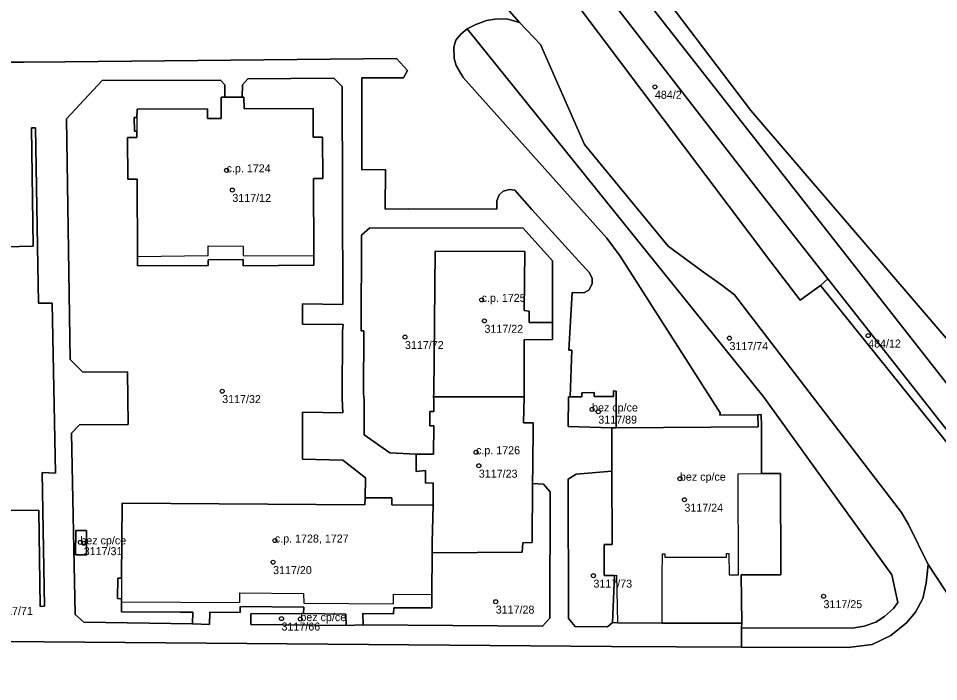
# Model space of a CAD drawing. Extents: x -878211 to -870363, y -1058464 to -1052522.
# Drawn here: x -874067.3 to -873952.4, y -1056770.5 to -1056687.6 of the extents above; entities that cross this region are included whole.
import ezdxf

# ---------------------------------------------------------------- set-up
doc = ezdxf.new("R2010")
doc.units = 0
for name, color, linetype in [('Vrstva 50', 7, 'Continuous'), ('Vrstva 51', 7, 'Continuous'), ('Vrstva 52', 7, 'Continuous')]:
    doc.layers.add(name, color=color, linetype=linetype)

msp = doc.modelspace()

# ---------------------------------------------------------------- linework, layer by layer
at = {"layer": 'Vrstva 50'}
for centre in [(-873987.81, -1056696.11994), (-874041.33, -1056706.55994), (-874040.61, -1056709.01994), (-874009.46, -1056722.75994), (-874009.11, -1056725.38994), (-873961.16, -1056727.22994), (-874019.04, -1056727.41994), (-873978.49, -1056727.54994), (-874041.88, -1056734.17994), (-873995.66, -1056736.46994), (-873994.88, -1056736.74994), (-874010.16, -1056741.81994), (-874009.81, -1056743.50994), (-873984.68, -1056745.12994), (-873984.12, -1056747.75994), (-874059.6, -1056753.08994), (-874059.18, -1056753.19994), (-874035.3, -1056752.85994), (-874035.52, -1056755.56994), (-873995.49, -1056757.25994), (-874007.7, -1056760.50994), (-873966.74, -1056759.82994), (-874034.47, -1056762.62994), (-874032.11, -1056762.68994)]:
    msp.add_circle(centre, 0.25, dxfattribs=at)
at = {"layer": 'Vrstva 51'}
for points in [[(-873895.24, -1056850.14), (-873908.21, -1056824.62), (-873940.24, -1056755.07), (-873950.29, -1056741.89), (-873967.11, -1056720.96), (-873969.65, -1056722.8), (-873973.32, -1056718.02), (-874002.89, -1056678.66), (-874011.69, -1056666.89), (-874009.12, -1056664.87), (-874011.97, -1056661.51), (-874024.62, -1056638.91), (-874042.06, -1056605.74), (-874043.43, -1056601.67), (-874041.78, -1056601.01), (-874055.1, -1056577.75), (-874058.74, -1056569.35), (-874056.05, -1056577), (-874084.77, -1056524.21), (-874108.38, -1056481.4), (-874117.36, -1056461.73), (-874136.62, -1056429.22), (-874154.14, -1056399.02)], [(-874089.4, -1056424.57), (-874093.72, -1056425.61), (-874091.26, -1056427.37), (-874086.97, -1056446.13), (-874080.24, -1056469.1), (-874069.52, -1056495.93), (-874059.02, -1056523.78), (-874058.03, -1056527.95), (-874058.67, -1056530.92), (-874056.84, -1056534.05), (-874035.88, -1056579.88), (-874041.25, -1056593.06), (-874019.42, -1056638.08), (-874011.45, -1056652.11), (-873975.84, -1056699.09), (-873943.35, -1056736.97), (-873935.01, -1056752.39), (-873930.75, -1056761.9), (-873920.07, -1056788.11), (-873906.75, -1056817.03), (-873873.73, -1056840.56), (-873864.45, -1056848.53)], [(-874014.31, -1056677.14), (-874004.71, -1056688.09), (-874002.11, -1056690.82), (-873996.61, -1056703.34), (-873986.17, -1056716.03), (-873981.92, -1056719.15), (-873979.44, -1056720.92), (-873977.85, -1056722.15), (-873956.98, -1056749.34), (-873956.1, -1056750.86), (-873953.68, -1056755.84), (-873944.9, -1056769.17), (-873942.05, -1056774.1), (-873933.03, -1056790.26), (-873924.36, -1056807.24), (-873919, -1056817.58), (-873911.57, -1056832.96), (-873905.95, -1056847.41), (-873904.55, -1056852.25)], [(-874006.79, -1056709.15), (-874005.96, -1056708.95), (-874005.31, -1056709.05), (-874003.17, -1056711.45), (-873998.18, -1056716.96), (-873995.99, -1056719.37), (-873995.65, -1056720.1), (-873995.63, -1056720.74), (-873996.08, -1056721.54), (-873996.7, -1056721.88), (-873998.16, -1056721.82), (-873998.57, -1056729.04), (-873998.2, -1056729.05), (-873998.39, -1056734.88), (-873996.92, -1056734.87), (-873996.92, -1056734.37), (-873995.41, -1056734.36), (-873995.4, -1056734.86), (-873992.99, -1056734.85), (-873992.99, -1056734.15), (-873992.65, -1056734.17), (-873992.66, -1056738.77), (-873974.92, -1056738.65), (-873974.94, -1056737.15), (-873979.68, -1056737.2), (-873979.66, -1056736.88), (-873992.15, -1056717.29), (-873993.83, -1056715.06), (-874011.75, -1056694.95), (-874012.65, -1056693.44), (-874012.88, -1056692.58), (-874012.94, -1056691.15), (-874012.68, -1056690.27), (-874012.04, -1056689.51), (-874011.26, -1056688.86), (-874010.19, -1056688.31), (-874008.87, -1056687.8), (-874007.82, -1056687.66), (-874006.3, -1056687.63), (-874004.71, -1056688.09), (-874014.31, -1056677.14)], [(-874075.19, -1056765.47), (-874064.13, -1056765.55), (-873993.23, -1056766.12), (-873976.97, -1056766.19), (-873976.99, -1056763.76), (-873976.96, -1056763.19), (-873986.89, -1056763.18), (-873992.48, -1056763.15), (-873993.11, -1056763.12), (-873993.72, -1056763.66), (-873997.78, -1056763.61), (-873998.62, -1056762.6), (-873998.66, -1056745.19), (-873997.63, -1056744.54), (-873993.19, -1056744.19), (-873993.19, -1056742.14), (-873993.2, -1056738.75), (-873998.64, -1056738.58), (-873998.6, -1056734.88), (-873998.39, -1056734.88), (-873998.2, -1056729.05), (-873998.57, -1056729.04), (-873998.16, -1056721.82), (-873996.7, -1056721.88), (-873996.08, -1056721.54), (-873995.63, -1056720.74), (-873995.65, -1056720.1), (-873995.99, -1056719.37), (-873998.18, -1056716.96), (-874003.17, -1056711.45), (-874005.31, -1056709.05), (-874005.96, -1056708.95), (-874006.79, -1056709.15), (-874007.29, -1056709.63), (-874007.55, -1056710.38), (-874007.57, -1056711.41), (-874018.54, -1056711.37), (-874021.5, -1056711.41), (-874021.48, -1056706.46), (-874024.42, -1056706.5), (-874024.45, -1056695), (-874019.21, -1056694.97), (-874018.72, -1056694.09), (-874020.08, -1056692.58), (-874061.51, -1056692.97), (-874066.68, -1056693.03), (-874070.38, -1056693.05)], [(-874070.38, -1056693.05), (-874066.68, -1056693.03), (-874061.51, -1056692.97), (-874020.08, -1056692.58), (-874018.72, -1056694.09), (-874019.21, -1056694.97), (-874024.45, -1056695), (-874024.42, -1056706.5), (-874021.48, -1056706.46), (-874021.5, -1056711.41), (-874018.54, -1056711.37), (-874007.57, -1056711.41), (-874007.55, -1056710.38), (-874007.29, -1056709.63), (-874006.79, -1056709.15)], [(-874071.75, -1056749.13), (-874064.8, -1056749.07), (-874064.64, -1056761.09), (-874064.1, -1056761.07), (-874064.38, -1056744.35), (-874062.69, -1056744.43), (-874063.12, -1056723.16), (-874064.85, -1056723.19), (-874064.96, -1056716.03), (-874065.22, -1056701.24), (-874065.72, -1056701.25), (-874065.49, -1056716.05), (-874069, -1056716.13)], [(-874069, -1056716.13), (-874065.49, -1056716.05), (-874065.72, -1056701.25), (-874065.22, -1056701.24), (-874064.96, -1056716.03), (-874064.85, -1056723.19), (-874063.12, -1056723.16), (-874062.69, -1056744.43), (-874064.38, -1056744.35), (-874064.1, -1056761.07), (-874064.64, -1056761.09), (-874064.8, -1056749.07), (-874071.75, -1056749.13)], [(-873944.9, -1056769.17), (-873953.68, -1056755.84), (-873953.9, -1056758.19), (-873954.33, -1056760.1), (-873955.25, -1056761.8), (-873956.36, -1056763.16), (-873958.32, -1056764.75), (-873960.66, -1056765.87), (-873963.66, -1056766.24), (-873976.97, -1056766.19), (-873993.23, -1056766.12), (-874064.13, -1056765.55)], [(-874064.13, -1056765.55), (-874075.19, -1056765.47)]]:
    msp.add_lwpolyline(points, dxfattribs=at)
for points in [[(-874058.74, -1056569.35), (-874055.1, -1056577.75), (-874041.78, -1056601.01), (-874035.4, -1056613.17), (-874011.89, -1056655.9), (-873946.72, -1056739.16), (-873936.35, -1056752.76), (-873920.07, -1056788.11), (-873930.75, -1056761.9), (-873935.01, -1056752.39), (-873943.35, -1056736.97), (-873975.84, -1056699.09), (-874011.45, -1056652.11), (-874019.42, -1056638.08), (-874041.25, -1056593.06), (-874035.88, -1056579.88), (-874056.84, -1056534.05), (-874058.67, -1056530.92), (-874073.61, -1056527.53), (-874066.94, -1056541.99)], [(-873949.55, -1056741.32), (-873946.72, -1056739.16), (-874011.89, -1056655.9), (-874035.4, -1056613.17), (-874024.62, -1056638.91), (-874011.97, -1056661.51), (-874009.12, -1056664.87), (-873993.83, -1056684.56), (-873974.58, -1056709.46), (-873966.18, -1056720.11)], [(-874009.12, -1056664.87), (-874011.69, -1056666.89), (-874002.89, -1056678.66), (-873973.32, -1056718.02), (-873969.65, -1056722.8), (-873967.11, -1056720.96), (-873966.18, -1056720.11), (-873974.58, -1056709.46), (-873993.83, -1056684.56)], [(-873953.68, -1056755.84), (-873956.1, -1056750.86), (-873956.98, -1056749.34), (-873977.85, -1056722.15), (-873979.44, -1056720.92), (-873981.92, -1056719.15), (-873986.17, -1056716.03), (-873996.61, -1056703.34), (-874002.11, -1056690.82), (-874004.71, -1056688.09), (-874006.3, -1056687.63), (-874007.82, -1056687.66), (-874008.87, -1056687.8), (-874010.19, -1056688.31), (-874011.26, -1056688.86), (-873974.18, -1056734.93), (-873958.22, -1056757.15), (-873957.47, -1056760.63), (-873958, -1056761.37), (-873959.1, -1056762.36), (-873960.22, -1056763.05), (-873961.67, -1056763.57), (-873963.14, -1056763.82), (-873976.99, -1056763.76), (-873976.97, -1056766.19), (-873963.66, -1056766.24), (-873960.66, -1056765.87), (-873958.32, -1056764.75), (-873956.36, -1056763.16), (-873955.25, -1056761.8), (-873954.33, -1056760.1), (-873953.9, -1056758.19)], [(-873958.22, -1056757.15), (-873974.18, -1056734.93), (-874011.26, -1056688.86), (-874012.04, -1056689.51), (-874012.68, -1056690.27), (-874012.94, -1056691.15), (-874012.88, -1056692.58), (-874012.65, -1056693.44), (-874011.75, -1056694.95), (-873993.83, -1056715.06), (-873992.15, -1056717.29), (-873979.66, -1056736.88), (-873979.68, -1056737.2), (-873974.94, -1056737.15), (-873974.55, -1056737.11), (-873974.5, -1056738.6), (-873974.5, -1056744.46), (-873972.11, -1056744.48), (-873972.09, -1056757.14), (-873977.03, -1056757.17), (-873976.96, -1056763.19), (-873976.99, -1056763.76), (-873963.14, -1056763.82), (-873961.67, -1056763.57), (-873960.22, -1056763.05), (-873959.1, -1056762.36), (-873958, -1056761.37), (-873957.47, -1056760.63)], [(-874039.4, -1056697.4), (-874039.16, -1056697.4), (-874039.15, -1056698.86), (-874030.53, -1056698.81), (-874030.51, -1056702.4), (-874029.33, -1056702.4), (-874029.31, -1056707.59), (-874030.49, -1056707.6), (-874030.44, -1056717.24), (-874030.43, -1056718.44), (-874039.27, -1056718.49), (-874039.26, -1056717.7), (-874043.63, -1056717.74), (-874043.64, -1056718.48), (-874052.45, -1056718.52), (-874052.45, -1056717.33), (-874052.49, -1056707.66), (-874053.67, -1056707.67), (-874053.71, -1056702.47), (-874052.53, -1056702.46), (-874052.54, -1056701.66), (-874052.84, -1056701.66), (-874052.86, -1056699.97), (-874052.53, -1056699.97), (-874052.51, -1056698.89), (-874043.71, -1056698.88), (-874043.71, -1056700.08), (-874042, -1056700.06), (-874042.01, -1056697.41), (-874041.54, -1056697.41), (-874041.54, -1056695.87), (-874042.11, -1056695.27), (-874056.86, -1056695.33), (-874061.35, -1056700.1), (-874060.88, -1056730.22), (-874059.29, -1056731.82), (-874053.7, -1056731.77), (-874053.63, -1056738.34), (-874059.69, -1056738.37), (-874060.7, -1056739.45), (-874060.26, -1056762.1), (-874059.15, -1056763.09), (-874045.57, -1056763.27), (-874045.56, -1056761.8), (-874047.12, -1056761.81), (-874054.47, -1056761.79), (-874054.47, -1056760.51), (-874054.47, -1056760.15), (-874054.97, -1056760.13), (-874054.9, -1056757.56), (-874054.45, -1056757.57), (-874054.37, -1056748.17), (-874024.04, -1056748.4), (-874024.02, -1056747.5), (-874023.98, -1056745.03), (-874026.82, -1056742.8), (-874031.86, -1056742.68), (-874031.83, -1056736.82), (-874026.79, -1056736.89), (-874026.87, -1056735.1), (-874026.86, -1056726.66), (-874026.77, -1056725.84), (-874031.83, -1056725.78), (-874031.83, -1056723.25), (-874026.81, -1056723.32), (-874026.87, -1056696.06), (-874027.94, -1056695.03), (-874038.66, -1056695.12), (-874039.35, -1056695.88)], [(-874041.54, -1056697.41), (-874039.4, -1056697.4), (-874039.35, -1056695.88), (-874038.66, -1056695.12), (-874027.94, -1056695.03), (-874026.87, -1056696.06), (-874026.81, -1056723.32), (-874031.83, -1056723.25), (-874031.83, -1056725.78), (-874026.77, -1056725.84), (-874026.86, -1056726.66), (-874026.87, -1056735.1), (-874026.79, -1056736.89), (-874031.83, -1056736.82), (-874031.86, -1056742.68), (-874026.82, -1056742.8), (-874023.98, -1056745.03), (-874024.02, -1056747.5), (-874020.67, -1056747.51), (-874020.69, -1056748.41), (-874015.5, -1056748.43), (-874015.51, -1056745.65), (-874016.47, -1056745.69), (-874016.48, -1056744.12), (-874017.65, -1056744.22), (-874017.66, -1056742.06), (-874020.93, -1056741.9), (-874024.12, -1056739.66), (-874024.16, -1056735.24), (-874024.19, -1056734.92), (-874024.22, -1056734.41), (-874024.19, -1056726.64), (-874024.52, -1056726.64), (-874024.46, -1056714.67), (-874023.43, -1056713.77), (-874004.29, -1056713.78), (-874000.6, -1056717.89), (-874000.62, -1056725.59), (-874000.61, -1056727.71), (-874004.13, -1056727.74), (-874004.14, -1056734.65), (-874004.14, -1056734.9), (-874004.21, -1056738.14), (-874003.03, -1056738.14), (-874003.04, -1056738.57), (-874003.07, -1056743.57), (-874003.09, -1056745.72), (-874001.75, -1056745.82), (-874000.89, -1056746.78), (-874000.92, -1056762.59), (-874001.86, -1056763.57), (-874024.26, -1056763.4), (-874026.37, -1056763.49), (-874038.31, -1056763.35), (-874038.31, -1056762.02), (-874031.7, -1056761.97), (-874031.68, -1056761.19), (-874039.62, -1056761.1), (-874039.62, -1056761.86), (-874043.44, -1056761.84), (-874043.48, -1056763.35), (-874045.57, -1056763.27), (-874059.15, -1056763.09), (-874060.26, -1056762.1), (-874060.7, -1056739.45), (-874059.69, -1056738.37), (-874053.63, -1056738.34), (-874053.7, -1056731.77), (-874059.29, -1056731.82), (-874060.88, -1056730.22), (-874061.35, -1056700.1), (-874056.86, -1056695.33), (-874042.11, -1056695.27), (-874041.54, -1056695.87)], [(-874039.15, -1056698.86), (-874039.16, -1056697.4), (-874039.4, -1056697.4), (-874041.54, -1056697.41), (-874042.01, -1056697.41), (-874042, -1056700.06), (-874043.71, -1056700.08), (-874043.71, -1056698.88), (-874052.51, -1056698.89), (-874052.53, -1056699.97), (-874052.86, -1056699.97), (-874052.84, -1056701.66), (-874052.54, -1056701.66), (-874052.53, -1056702.46), (-874053.71, -1056702.47), (-874053.67, -1056707.67), (-874052.49, -1056707.66), (-874052.45, -1056717.33), (-874052.45, -1056718.52), (-874043.64, -1056718.48), (-874043.63, -1056717.74), (-874039.26, -1056717.7), (-874039.27, -1056718.49), (-874030.43, -1056718.44), (-874030.44, -1056717.24), (-874030.49, -1056707.6), (-874029.31, -1056707.59), (-874029.33, -1056702.4), (-874030.51, -1056702.4), (-874030.53, -1056698.81)], [(-874015.46, -1056734.88), (-874015.45, -1056734.47), (-874015.27, -1056716.67), (-874004.08, -1056716.71), (-874004.14, -1056724.09), (-874003.53, -1056724.18), (-874003.54, -1056725.6), (-874000.62, -1056725.59), (-874000.6, -1056717.89), (-874004.29, -1056713.78), (-874023.43, -1056713.77), (-874024.46, -1056714.67), (-874024.52, -1056726.64), (-874024.19, -1056726.64), (-874024.22, -1056734.41), (-874024.19, -1056734.92), (-874024.16, -1056735.24), (-874024.12, -1056739.66), (-874020.93, -1056741.9), (-874017.66, -1056742.06), (-874015.48, -1056742.05), (-874015.44, -1056738.5), (-874015.95, -1056738.51), (-874015.93, -1056736.72), (-874015.44, -1056736.73), (-874015.45, -1056735.23)], [(-874004.14, -1056734.9), (-874004.14, -1056734.65), (-874004.13, -1056727.74), (-874000.61, -1056727.71), (-874000.62, -1056725.59), (-874003.54, -1056725.6), (-874003.53, -1056724.18), (-874004.14, -1056724.09), (-874004.08, -1056716.71), (-874015.27, -1056716.67), (-874015.45, -1056734.47), (-874015.46, -1056734.88)], [(-873967.11, -1056720.96), (-873950.29, -1056741.89), (-873949.55, -1056741.32), (-873966.18, -1056720.11)], [(-874017.66, -1056742.06), (-874017.65, -1056744.22), (-874016.48, -1056744.12), (-874016.47, -1056745.69), (-874015.51, -1056745.65), (-874015.5, -1056748.43), (-874015.63, -1056753.09), (-874015.64, -1056754.39), (-874004.38, -1056754.3), (-874004.31, -1056753.15), (-874003.14, -1056753.1), (-874003.09, -1056745.72), (-874003.07, -1056743.57), (-874003.04, -1056738.57), (-874003.03, -1056738.14), (-874004.21, -1056738.14), (-874004.14, -1056734.9), (-874015.46, -1056734.88), (-874015.45, -1056735.23), (-874015.44, -1056736.73), (-874015.93, -1056736.72), (-874015.95, -1056738.51), (-874015.44, -1056738.5), (-874015.48, -1056742.05)], [(-873998.6, -1056734.88), (-873998.64, -1056738.58), (-873993.2, -1056738.75), (-873992.66, -1056738.77), (-873992.65, -1056734.17), (-873992.99, -1056734.15), (-873992.99, -1056734.85), (-873995.4, -1056734.86), (-873995.41, -1056734.36), (-873996.92, -1056734.37), (-873996.92, -1056734.87), (-873998.39, -1056734.88)], [(-873993.19, -1056744.19), (-873993.15, -1056753.36), (-873994.13, -1056753.37), (-873994.15, -1056757.25), (-873992.85, -1056757.22), (-873993.11, -1056763.12), (-873992.48, -1056763.15), (-873986.89, -1056763.18), (-873976.96, -1056763.19), (-873977.03, -1056757.17), (-873972.09, -1056757.14), (-873972.11, -1056744.48), (-873974.5, -1056744.46), (-873974.5, -1056738.6), (-873974.55, -1056737.11), (-873974.94, -1056737.15), (-873974.92, -1056738.65), (-873992.66, -1056738.77), (-873993.2, -1056738.75), (-873993.19, -1056742.14)], [(-873993.11, -1056763.12), (-873992.85, -1056757.22), (-873994.15, -1056757.25), (-873994.13, -1056753.37), (-873993.15, -1056753.36), (-873993.19, -1056744.19), (-873997.63, -1056744.54), (-873998.66, -1056745.19), (-873998.62, -1056762.6), (-873997.78, -1056763.61), (-873993.72, -1056763.66)], [(-874003.09, -1056745.72), (-874003.14, -1056753.1), (-874004.31, -1056753.15), (-874004.38, -1056754.3), (-874015.64, -1056754.39), (-874015.67, -1056759.59), (-874015.68, -1056761.28), (-874020.45, -1056761.27), (-874020.48, -1056762.01), (-874024.29, -1056762), (-874024.26, -1056763.4), (-874001.86, -1056763.57), (-874000.92, -1056762.59), (-874000.89, -1056746.78), (-874001.75, -1056745.82)], [(-874039.62, -1056761.86), (-874039.62, -1056761.1), (-874031.68, -1056761.19), (-874031.7, -1056761.97), (-874026.44, -1056762.07), (-874026.37, -1056763.49), (-874024.26, -1056763.4), (-874024.29, -1056762), (-874020.48, -1056762.01), (-874020.45, -1056761.27), (-874015.68, -1056761.28), (-874015.67, -1056759.59), (-874015.64, -1056754.39), (-874015.63, -1056753.09), (-874015.5, -1056748.43), (-874020.69, -1056748.41), (-874020.67, -1056747.51), (-874024.02, -1056747.5), (-874024.04, -1056748.4), (-874054.37, -1056748.17), (-874054.45, -1056757.57), (-874054.9, -1056757.56), (-874054.97, -1056760.13), (-874054.47, -1056760.15), (-874054.47, -1056760.51), (-874054.47, -1056761.79), (-874047.12, -1056761.81), (-874045.56, -1056761.8), (-874045.57, -1056763.27), (-874043.48, -1056763.35), (-874043.44, -1056761.84)], [(-874058.85, -1056754.64), (-874058.83, -1056751.61), (-874060.18, -1056751.59), (-874060.21, -1056754.66)], [(-874058.85, -1056754.64), (-874060.21, -1056754.66), (-874060.18, -1056751.59), (-874058.83, -1056751.61)], [(-874026.37, -1056763.49), (-874026.44, -1056762.07), (-874031.7, -1056761.97), (-874038.31, -1056762.02), (-874038.31, -1056763.35)]]:
    msp.add_lwpolyline(points, close=True, dxfattribs=at)
at = {"layer": 'Vrstva 52'}
for points in [[(-874053.71, -1056702.47), (-874053.67, -1056707.67), (-874052.49, -1056707.66), (-874052.45, -1056717.33), (-874043.64, -1056717.22), (-874043.65, -1056716.02), (-874039.26, -1056716.03), (-874039.26, -1056717.23), (-874030.44, -1056717.24), (-874030.49, -1056707.6), (-874029.31, -1056707.59), (-874029.33, -1056702.4), (-874030.51, -1056702.4), (-874030.53, -1056698.81), (-874039.15, -1056698.86), (-874039.16, -1056697.4), (-874039.4, -1056697.4), (-874041.54, -1056697.41), (-874042.01, -1056697.41), (-874042, -1056700.06), (-874043.71, -1056700.08), (-874043.71, -1056698.88), (-874052.51, -1056698.89), (-874052.53, -1056699.97), (-874052.54, -1056701.66), (-874052.53, -1056702.46)], [(-874003.53, -1056724.18), (-874004.14, -1056724.09), (-874004.08, -1056716.71), (-874015.27, -1056716.67), (-874015.45, -1056734.47), (-874015.46, -1056734.88), (-874004.14, -1056734.9), (-874004.14, -1056734.65), (-874004.13, -1056727.74), (-874000.61, -1056727.71), (-874000.62, -1056725.59), (-874003.54, -1056725.6)], [(-874017.66, -1056742.06), (-874017.65, -1056744.22), (-874016.48, -1056744.12), (-874016.47, -1056745.69), (-874015.51, -1056745.65), (-874015.5, -1056748.43), (-874015.63, -1056753.09), (-874015.64, -1056754.39), (-874004.38, -1056754.3), (-874004.31, -1056753.15), (-874003.14, -1056753.1), (-874003.09, -1056745.72), (-874003.07, -1056743.57), (-874003.04, -1056738.57), (-874003.03, -1056738.14), (-874004.21, -1056738.14), (-874004.14, -1056734.9), (-874015.46, -1056734.88), (-874015.45, -1056735.23), (-874015.44, -1056736.73), (-874015.93, -1056736.72), (-874015.95, -1056738.51), (-874015.44, -1056738.5), (-874015.48, -1056742.05)], [(-873998.64, -1056738.58), (-873993.2, -1056738.75), (-873992.66, -1056738.77), (-873992.65, -1056734.17), (-873992.99, -1056734.15), (-873992.99, -1056734.85), (-873995.4, -1056734.86), (-873995.41, -1056734.36), (-873996.92, -1056734.37), (-873996.92, -1056734.87), (-873998.39, -1056734.88), (-873998.6, -1056734.88)], [(-873978.86, -1056754.93), (-873978.86, -1056754.48), (-873978.56, -1056754.5), (-873978.51, -1056757.15), (-873977.38, -1056757.16), (-873977.42, -1056744.52), (-873974.5, -1056744.46), (-873974.5, -1056738.6), (-873974.55, -1056737.11), (-873974.94, -1056737.15), (-873974.92, -1056738.65), (-873992.66, -1056738.77), (-873993.2, -1056738.75), (-873993.19, -1056742.14), (-873993.19, -1056744.19), (-873993.15, -1056753.36), (-873994.13, -1056753.37), (-873994.15, -1056757.25), (-873992.85, -1056757.22), (-873992.59, -1056757.21), (-873992.48, -1056763.15), (-873986.89, -1056763.18), (-873986.92, -1056757.19), (-873986.88, -1056754.51), (-873986.57, -1056754.51), (-873986.57, -1056754.96)], [(-874031.7, -1056759.49), (-874031.69, -1056760.69), (-874020.47, -1056760.76), (-874020.46, -1056759.57), (-874015.67, -1056759.59), (-874015.64, -1056754.39), (-874015.63, -1056753.09), (-874015.5, -1056748.43), (-874020.69, -1056748.41), (-874020.67, -1056747.51), (-874024.02, -1056747.5), (-874024.04, -1056748.4), (-874054.37, -1056748.17), (-874054.45, -1056757.57), (-874054.47, -1056760.15), (-874054.47, -1056760.51), (-874039.69, -1056760.61), (-874039.69, -1056759.42)], [(-874060.21, -1056754.66), (-874058.85, -1056754.64), (-874058.83, -1056751.61), (-874060.18, -1056751.59)], [(-874026.44, -1056762.07), (-874031.7, -1056761.97), (-874038.31, -1056762.02), (-874038.31, -1056763.35), (-874026.37, -1056763.49)]]:
    msp.add_lwpolyline(points, close=True, dxfattribs=at)
msp.add_lwpolyline([(-874071.75, -1056749.13), (-874064.8, -1056749.07), (-874064.64, -1056761.09), (-874064.1, -1056761.07), (-874064.38, -1056744.35), (-874062.69, -1056744.43), (-874063.12, -1056723.16), (-874064.85, -1056723.19), (-874064.96, -1056716.03), (-874065.22, -1056701.24), (-874065.72, -1056701.25), (-874065.49, -1056716.05), (-874069, -1056716.13)], dxfattribs=at)

# ---------------------------------------------------------------- texts
at = {"layer": 'Vrstva 50'}
for s, p in [('484/2', (-873987.81, -1056697.609)), ('c.p. 1724', (-874041.33, -1056706.81)), ('3117/12', (-874040.61, -1056710.509)), ('c.p. 1725', (-874009.46, -1056723.01)), ('3117/22', (-874009.11, -1056726.879)), ('3117/72', (-874019.04, -1056728.909)), ('3117/74', (-873978.49, -1056729.039)), ('484/12', (-873961.16, -1056728.719)), ('3117/32', (-874041.88, -1056735.669)), ('bez cp/ce', (-873995.66, -1056736.72)), ('3117/89', (-873994.88, -1056738.239)), ('c.p. 1726', (-874010.16, -1056742.07)), ('3117/23', (-874009.81, -1056744.999)), ('bez cp/ce', (-873984.68, -1056745.379)), ('3117/24', (-873984.12, -1056749.249)), ('bez cp/ce', (-874059.6, -1056753.34)), ('c.p. 1728, 1727', (-874035.3, -1056753.11)), ('3117/31', (-874059.18, -1056754.689)), ('3117/20', (-874035.52, -1056757.059)), ('3117/73', (-873995.49, -1056758.749)), ('3117/25', (-873966.74, -1056761.319)), ('3117/71', (-874070.37, -1056762.159)), ('3117/28', (-874007.7, -1056761.999)), ('bez cp/ce', (-874032.11, -1056762.94)), ('3117/66', (-874034.47, -1056764.119))]:
    msp.add_text(s, height=0.999996, dxfattribs=at).set_placement(p)

doc.saveas('drawing.dxf')
